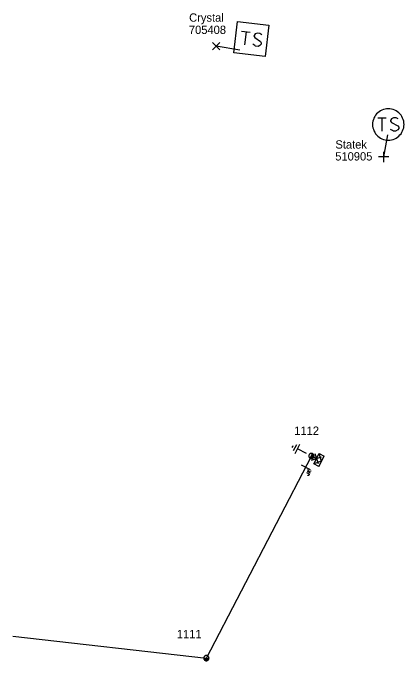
# Model space of a CAD drawing. Extents: x -545577 to -544860, y -1195056 to -1194677.
# Drawn here: x -545576.9 to -545529.9, y -1195056.2 to -1194978.2 of the extents above; entities that cross this region are included whole.
import ezdxf

# ---------------------------------------------------------------- set-up
doc = ezdxf.new("R2010")
doc.units = 0
for name, color, linetype in [('Vrstva 1', 7, 'Continuous'), ('Vrstva 13', 7, 'Continuous'), ('Vrstva 14', 7, 'Continuous'), ('Vrstva 15', 7, 'Continuous'), ('Vrstva 18', 7, 'Continuous'), ('Vrstva 2', 7, 'Continuous'), ('Vrstva 25', 7, 'Continuous'), ('Vrstva 26', 7, 'Continuous'), ('Vrstva 27', 7, 'Continuous'), ('Vrstva 31', 7, 'Continuous'), ('Vrstva 34', 7, 'Continuous'), ('Vrstva 50', 7, 'Continuous'), ('Vrstva 54', 7, 'Continuous'), ('Vrstva 59', 7, 'Continuous'), ('Vrstva 6', 7, 'Continuous'), ('Vrstva 9', 7, 'Continuous')]:
    doc.layers.add(name, color=color, linetype=linetype)

# ---------------------------------------------------------------- blocks, each defined once
blk = doc.blocks.new('NN440')
at = {"layer": 'Vrstva 2'}
for points in [[(0.63, 0), (0.63, 0.06), (0.62, 0.13), (0.6, 0.19), (0.58, 0.25), (0.55, 0.31), (0.51, 0.37), (0.47, 0.42), (0.42, 0.46), (0.37, 0.51), (0.32, 0.54), (0.26, 0.57), (0.2, 0.59), (0.13, 0.61), (0.07, 0.62), (0, 0.63), (-0.06, 0.62), (-0.13, 0.61), (-0.19, 0.59), (-0.26, 0.57), (-0.31, 0.54), (-0.37, 0.51), (-0.42, 0.46), (-0.47, 0.42), (-0.51, 0.37), (-0.54, 0.31), (-0.57, 0.25), (-0.6, 0.19), (-0.62, 0.13), (-0.63, 0.06), (-0.63, 0), (-0.63, -0.07), (-0.62, -0.14), (-0.6, -0.2), (-0.57, -0.26), (-0.54, -0.32), (-0.51, -0.37), (-0.47, -0.43), (-0.42, -0.47), (-0.37, -0.51), (-0.31, -0.55), (-0.26, -0.58), (-0.19, -0.6), (-0.13, -0.62), (-0.06, -0.63), (0, -0.63), (0.07, -0.63), (0.13, -0.62), (0.2, -0.6), (0.26, -0.58), (0.32, -0.55), (0.37, -0.51), (0.42, -0.47), (0.47, -0.43), (0.51, -0.37), (0.55, -0.32), (0.58, -0.26), (0.6, -0.2), (0.62, -0.14), (0.63, -0.07), (0.63, 0)], [(-0.63, 0), (0.63, 0)], [(-0.6, -0.18), (0.57, -0.18)], [(-0.51, -0.32), (0.5, -0.32)], [(-0.37, -0.47), (0.35, -0.47)]]:
    blk.add_lwpolyline(points, dxfattribs=at)
blk = doc.blocks.new('NN840')
at = {"layer": 'Vrstva 15'}
for points in [[(0.003, 0.619), (0.003, -0.631)], [(-0.745, -0.71), (-0.745, -0.66)], [(-0.73, -0.764), (-0.745, -0.71)], [(-0.657, -0.798), (-0.73, -0.764)], [(-0.558, -0.764), (-0.627, -0.798)], [(-0.538, -0.71), (-0.558, -0.764)], [(-0.538, -0.385), (-0.538, -0.71)], [(-0.332, -0.385), (-0.332, -0.798)], [(-0.332, -0.641), (-0.125, -0.385)], [(-0.263, -0.557), (-0.091, -0.798)], [(-0.627, -0.798), (-0.657, -0.798)]]:
    blk.add_lwpolyline(points, dxfattribs=at)
blk = doc.blocks.new('NN800')
at = {"layer": 'Vrstva 1'}
for points in [[(-0.442, 0.442), (0.442, -0.442)], [(-0.442, -0.442), (0.442, 0.442)]]:
    blk.add_lwpolyline(points, dxfattribs=at)
blk = doc.blocks.new('NN630')
at = {"layer": 'Vrstva 9'}
for points in [[(-0.003, -0.7), (-0.703, 0)], [(-0.703, -0.7), (-0.703, 0), (0.697, 0), (0.697, -0.7)], [(-0.703, -0.7), (0.697, -0.7)], [(-0.003, -0.7), (0.697, 0)]]:
    blk.add_lwpolyline(points, dxfattribs=at)
blk = doc.blocks.new('NN810')
at = {"layer": 'Vrstva 14'}
for points in [[(0.004, -0.64), (0.004, -1.89)], [(0.629, -1.89), (-0.621, -1.89)], [(0.388, -2.2), (-0.399, -2.2)], [(0.004, -2.515), (-0.124, -2.515)], [(0.137, -2.515), (0.004, -2.515)]]:
    blk.add_lwpolyline(points, dxfattribs=at)
blk = doc.blocks.new('NN640')
at = {"layer": 'Vrstva 6'}
for points in [[(-1.89, 1.889), (1.889, 1.889)], [(-1.89, -1.89), (-1.89, 1.889)], [(1.889, 1.889), (1.889, -1.89)], [(-1.26, 0.787), (-0.221, 0.787)], [(-0.725, 0.787), (-0.725, -0.788)], [(1.197, 0.661), (0.945, 0.787), (0.661, 0.787), (0.409, 0.661), (0.283, 0.472), (0.283, 0.409), (0.409, 0.22), (1.133, -0.158), (1.259, -0.316), (1.259, -0.473), (1.133, -0.662), (0.913, -0.788), (0.629, -0.788), (0.503, -0.725), (0.283, -0.599)], [(1.889, -1.89), (-1.89, -1.89)]]:
    blk.add_lwpolyline(points, dxfattribs=at)
blk = doc.blocks.new('NN610')
at = {"layer": 'Vrstva 6'}
for points in [[(1.883, -0.001), (1.872, 0.196), (1.841, 0.392), (1.79, 0.583), (1.718, 0.768), (1.629, 0.943), (1.521, 1.109), (1.397, 1.263), (1.257, 1.403), (1.103, 1.527), (0.937, 1.635), (0.761, 1.725), (0.577, 1.796), (0.19, 1.878), (0.19, 1.878), (-0.007, 1.889), (-0.205, 1.878), (-0.401, 1.847), (-0.591, 1.796), (-0.777, 1.725), (-0.952, 1.635), (-1.118, 1.527), (-1.272, 1.403), (-1.412, 1.263), (-1.536, 1.109), (-1.644, 0.943), (-1.734, 0.768), (-1.805, 0.583), (-1.856, 0.392), (-1.887, 0.196), (-1.898, -0.001), (-1.887, -0.199), (-1.856, -0.395), (-1.805, -0.585), (-1.734, -0.77), (-1.644, -0.946), (-1.536, -1.112), (-1.411, -1.266), (-1.272, -1.405), (-1.118, -1.53), (-0.952, -1.638), (-0.776, -1.728), (-0.591, -1.799), (-0.401, -1.85), (-0.205, -1.881), (-0.007, -1.892), (0.19, -1.881), (0.385, -1.85), (0.577, -1.799), (0.761, -1.728), (0.937, -1.638), (1.103, -1.53), (1.257, -1.405), (1.397, -1.266), (1.521, -1.112), (1.629, -0.946), (1.718, -0.77), (1.79, -0.585), (1.841, -0.395), (1.872, -0.199), (1.883, -0.001)], [(-1.269, 0.782), (-0.261, 0.782)], [(-0.765, 0.782), (-0.765, -0.792)], [(1.188, 0.656), (0.936, 0.782), (0.621, 0.782), (0.369, 0.656), (0.243, 0.468), (0.243, 0.404), (0.369, 0.216), (1.125, -0.162), (1.251, -0.32), (1.251, -0.478), (1.125, -0.666), (0.873, -0.792), (0.621, -0.792), (0.495, -0.73), (0.243, -0.604)]]:
    blk.add_lwpolyline(points, dxfattribs=at)

msp = doc.modelspace()

# ---------------------------------------------------------------- linework, layer by layer
at = {"layer": 'Vrstva 50'}
msp.add_lwpolyline([(-545576.86, -1195053.153), (-545553.62, -1195055.812), (-545541, -1195031.512)], dxfattribs=at)
at = {"layer": 'Vrstva 54'}
msp.add_lwpolyline([(-545541, -1195031.512), (-545540.387, -1195031.812)], dxfattribs=at)
at = {"layer": 'Vrstva 59'}
for points in [[(-545549.586, -1194982.723), (-545552.447, -1194982.246)], [(-545531.856, -1194992.887), (-545532.321, -1194995.552)]]:
    msp.add_lwpolyline(points, dxfattribs=at)

# ---------------------------------------------------------------- block references
at = {"layer": 'Vrstva 13', "xscale": 0.5, "yscale": 0.5}
for p, rotation in [((-545541, -1195031.512), 62.555272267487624), ((-545553.62, -1195055.812), -6.526068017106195)]:
    msp.add_blockref('NN440', p, dxfattribs=dict(at, rotation=rotation))
at = {"layer": 'Vrstva 15', "rotation": -117.44472779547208}
msp.add_blockref('NN810', (-545541, -1195031.512), dxfattribs=at)
at = {"layer": 'Vrstva 18', "rotation": 62.555272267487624}
msp.add_blockref('NN840', (-545541.698, -1195032.855), dxfattribs=at)
at = {"layer": 'Vrstva 25'}
for name, p, rotation in [('NN640', (-545548.229, -1194981.375), -6.719183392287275), ('NN610', (-545531.75, -1194991.65), 0.014666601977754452)]:
    msp.add_blockref(name, p, dxfattribs=dict(at, rotation=rotation))
at = {"layer": 'Vrstva 31', "rotation": 62.555272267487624}
msp.add_blockref('NN630', (-545540.394, -1195031.826), dxfattribs=at)
at = {"layer": 'Vrstva 34'}
msp.add_blockref('NN800', (-545552.447, -1194982.246), dxfattribs=at)
for p, rotation in [((-545532.321, -1194995.552), -135.00000004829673), ((-545540.387, -1195031.812), -26.030787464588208)]:
    msp.add_blockref('NN800', p, dxfattribs=dict(at, rotation=rotation))

# ---------------------------------------------------------------- texts
at = {"layer": 'Vrstva 14'}
for s, p in [('1112', (-545543.059, -1195028.968)), ('1111', (-545557.17, -1195053.419))]:
    msp.add_text(s, height=1, dxfattribs=at).set_placement(p)
at = {"layer": 'Vrstva 26'}
msp.add_text('705408', height=1, dxfattribs=at).set_placement((-545555.721, -1194980.774))
msp.add_text('510905', height=1, rotation=0.015, dxfattribs=at).set_placement((-545538.132, -1194995.988))
at = {"layer": 'Vrstva 27'}
for s, p in [('Crystal', (-545555.691, -1194979.3)), ('Statek', (-545538.114, -1194994.554))]:
    msp.add_text(s, height=1, dxfattribs=at).set_placement(p)

doc.saveas('drawing.dxf')
